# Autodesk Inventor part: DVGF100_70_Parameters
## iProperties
Created: 2010-04
Part Number: DVGF100_70_Parameters
Document SubType Name: Modeling
Designer: TB
Density: 1 g/cm^3
Slaglengde: 100.000 mm
Vinkel_Plussport: 0.00 deg
Vinkel_Minusport: 0.00 deg
Forlengelse_rør: 0.000 mm
Author: TB
